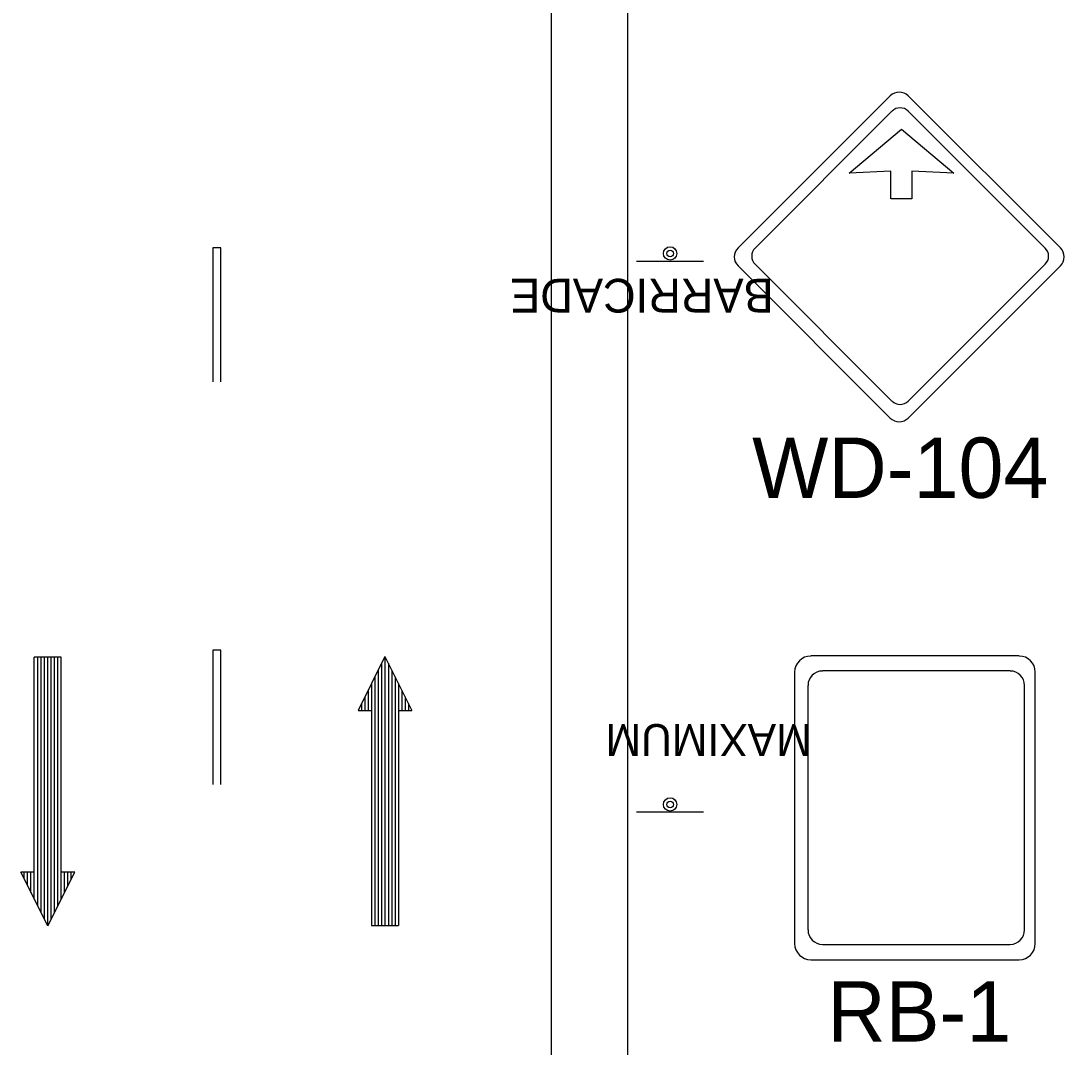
# Model space of a CAD drawing. Extents: x 797 to 1013, y 120 to 399.
# Drawn here: x 854.67 to 892.26, y 156.08 to 193.09 of the extents above; entities that cross this region are included whole.
import ezdxf

# ---------------------------------------------------------------- set-up
doc = ezdxf.new("R2010")
doc.units = 0
for name, color, linetype in [('Level 10', 7, 'Continuous'), ('Level 2', 7, 'Continuous'), ('Level 44', 7, 'Continuous')]:
    doc.layers.add(name, color=color, linetype=linetype)

msp = doc.modelspace()

# ---------------------------------------------------------------- linework, layer by layer
at = {"layer": 'Level 10'}
for p, q in [((873.779, 383.976), (873.779, 135.758)), ((876.533, 383.976), (876.533, 135.758)), ((855.154, 162.39), (855.154, 170.147)), ((856.124, 170.147), (855.154, 170.147)), ((855.154, 161.421), (855.154, 170.147)), ((855.275, 161.178), (855.275, 170.147)), ((855.397, 160.936), (855.397, 170.147)), ((855.518, 160.694), (855.518, 170.147)), ((855.639, 160.451), (855.639, 170.147)), ((855.76, 160.694), (855.76, 170.147)), ((855.881, 160.936), (855.881, 170.147)), ((856.003, 161.178), (856.003, 170.147)), ((856.124, 162.39), (856.124, 170.147)), ((856.124, 161.421), (856.124, 170.147)), ((867.79, 170.165), (866.821, 168.226)), ((867.669, 169.923), (867.669, 160.469)), ((867.79, 170.165), (867.79, 160.469)), ((867.79, 170.165), (868.76, 168.226)), ((867.912, 169.923), (867.912, 160.469)), ((867.548, 169.68), (867.548, 160.469)), ((868.033, 169.68), (868.033, 160.469)), ((867.306, 169.195), (867.306, 160.469)), ((867.427, 169.438), (867.427, 160.469)), ((868.154, 169.438), (868.154, 160.469)), ((868.275, 169.195), (868.275, 160.469)), ((867.184, 168.953), (867.184, 168.226)), ((868.396, 168.953), (868.396, 168.226)), ((866.942, 168.468), (866.942, 168.226)), ((867.063, 168.711), (867.063, 168.226)), ((868.518, 168.711), (868.518, 168.226)), ((868.639, 168.468), (868.639, 168.226)), ((866.821, 168.226), (867.306, 168.226)), ((867.306, 168.226), (867.306, 160.469)), ((868.275, 168.226), (868.275, 160.469)), ((868.275, 168.226), (868.76, 168.226)), ((855.639, 160.451), (854.669, 162.39)), ((855.154, 162.39), (854.669, 162.39)), ((854.791, 162.148), (854.791, 162.39)), ((854.912, 161.906), (854.912, 162.39)), ((855.033, 161.663), (855.033, 162.39)), ((855.639, 160.451), (856.609, 162.39)), ((856.609, 162.39), (856.124, 162.39)), ((856.245, 161.663), (856.245, 162.39)), ((856.366, 161.906), (856.366, 162.39)), ((856.487, 162.148), (856.487, 162.39)), ((867.306, 160.469), (868.275, 160.469))]:
    msp.add_line(p, q, dxfattribs=at)
at = {"layer": 'Level 2'}
for p, q in [((861.589, 184.908), (861.589, 180.07)), ((861.879, 184.908), (861.589, 184.908)), ((861.879, 180.07), (861.879, 184.908)), ((861.589, 170.394), (861.589, 165.556)), ((861.879, 170.394), (861.589, 170.394)), ((861.879, 165.556), (861.879, 170.394))]:
    msp.add_line(p, q, dxfattribs=at)
at = {"layer": 'Level 44'}
for p, q in [((880.514, 184.901), (885.994, 190.381)), ((886.643, 190.381), (892.132, 184.901)), ((886.059, 189.829), (881.125, 184.896)), ((891.582, 184.896), (886.643, 189.829)), ((884.515, 187.592), (886.401, 189.181)), ((886.401, 189.181), (888.287, 187.592)), ((886.023, 187.673), (884.515, 187.592)), ((886.023, 186.666), (886.023, 187.673)), ((888.287, 187.592), (886.779, 187.673)), ((886.779, 187.673), (886.779, 186.666)), ((886.779, 186.666), (886.028, 186.666)), ((876.849, 184.427), (879.273, 184.427)), ((885.994, 178.763), (880.514, 184.25)), ((881.125, 184.31), (886.059, 179.373)), ((886.643, 179.373), (891.582, 184.31)), ((892.132, 184.25), (886.643, 178.763)), ((892.127, 184.25), (892.132, 184.25)), ((890.644, 170.186), (883.132, 170.186)), ((882.551, 169.606), (882.551, 159.815)), ((890.315, 169.645), (883.555, 169.645)), ((891.223, 159.815), (891.223, 169.606)), ((883.032, 169.123), (883.032, 160.311)), ((890.836, 160.311), (890.836, 169.123)), ((876.849, 164.561), (879.273, 164.561)), ((890.836, 160.309), (890.836, 160.311)), ((883.555, 159.788), (890.315, 159.788)), ((891.223, 159.812), (891.223, 159.815)), ((883.132, 159.233), (890.644, 159.233))]:
    msp.add_line(p, q, dxfattribs=at)
for centre, radius in [((878.065, 184.699), 0.242), ((878.065, 184.699), 0.121), ((878.065, 164.832), 0.242), ((878.065, 164.832), 0.121)]:
    msp.add_circle(centre, radius, dxfattribs=at)
for centre, radius, start, end in [((886.32, 190.058), 0.459, 45, 135), ((886.352, 189.538), 0.413, 45, 135), ((880.836, 184.574), 0.459, 135, 225), ((881.417, 184.602), 0.413, 135, 225), ((891.288, 184.602), 0.413, 315, 45), ((891.804, 184.574), 0.459, 315, 45), ((886.352, 179.667), 0.413, 225, 315), ((886.32, 179.091), 0.459, 225, 315), ((883.132, 169.605), 0.58, 90, 180), ((890.643, 169.605), 0.58, 0, 90), ((883.555, 169.122), 0.522, 90, 180), ((890.315, 169.122), 0.522, 0, 90), ((883.555, 160.309), 0.522, 180, 270), ((890.315, 160.309), 0.522, 270, 0), ((883.132, 159.813), 0.58, 180, 270), ((890.643, 159.813), 0.58, 270, 0)]:
    msp.add_arc(centre, radius, start, end, dxfattribs=at)

# ---------------------------------------------------------------- texts
at = {"layer": 'Level 10'}
for s, p in [('WD-104', (881.019, 175.886)), ('RB-1', (883.727, 156.283))]:
    msp.add_text(s, height=2.1769, rotation=360, dxfattribs=at).set_placement(p)
at = {"layer": 'Level 44'}
for s, height, p in [('BARRICADE', 1.2169, (881.795, 183.786)), ('MAXIMUM', 1.149, (883.163, 167.732))]:
    msp.add_text(s, height=height, rotation=180, dxfattribs=at).set_placement(p)

doc.saveas('drawing.dxf')
